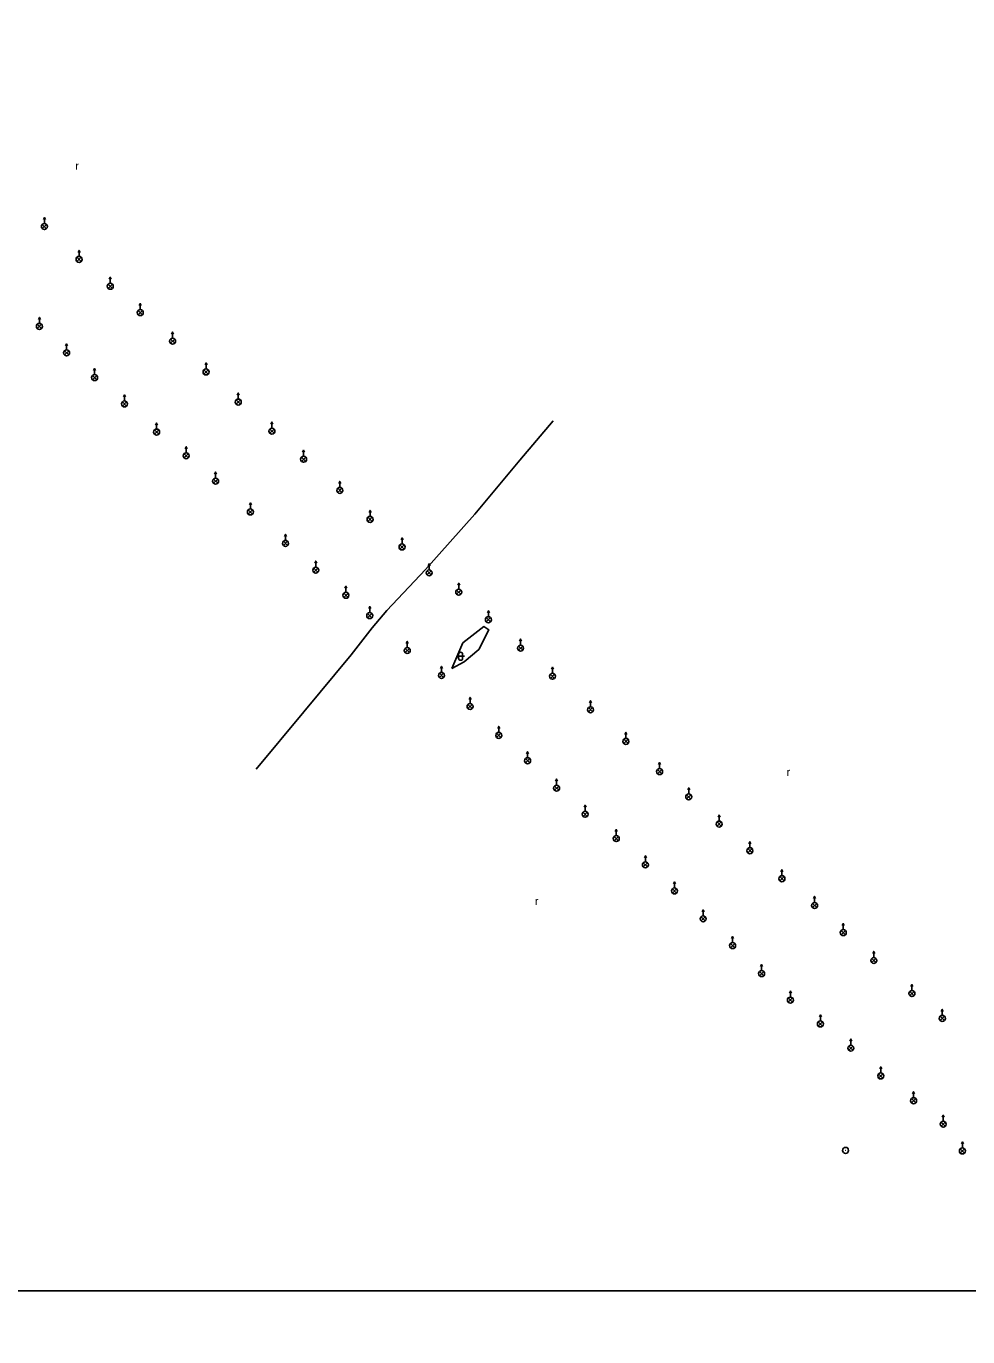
# Model space of a CAD drawing. Extents: x -582188 to -561562, y -1187250 to -1183500.
# Drawn here: x -578402.2 to -578284.6, y -1186755.7 to -1186592 of the extents above; entities that cross this region are included whole.
import ezdxf

# ---------------------------------------------------------------- set-up
doc = ezdxf.new("R2010")
doc.units = 0
for name, color, linetype in [('MAP_ZN_BP', 7, 'Continuous'), ('RÁMY_ML', 7, 'Continuous'), ('ZELEŇ', 7, 'Continuous'), ('ZN_BP', 7, 'Continuous'), ('ZN_KULTUR', 7, 'Continuous')]:
    doc.layers.add(name, color=color, linetype=linetype)

msp = doc.modelspace()

# ---------------------------------------------------------------- linework, layer by layer
at = {"layer": 'MAP_ZN_BP'}
for radius in [0.375, 0.0005]:
    msp.add_circle((-578299.84, -1186732.431), radius, dxfattribs=at)
at = {"layer": 'RÁMY_ML'}
msp.add_lwpolyline([(-578750, -1186250), (-578437.5, -1186250), (-578437.5, -1186500), (-578437.5, -1186750), (-578125, -1186750), (-578125, -1187000), (-578437.5, -1187000), (-578437.5, -1186750)], dxfattribs=at)
at = {"layer": 'ZELEŇ'}
for points in [[(-578352.3, -1186659.86), (-578346.17, -1186652.95), (-578340.51, -1186646.22), (-578336.37, -1186641.31)], [(-578352.3, -1186659.86), (-578357.15, -1186664.98), (-578358.96, -1186667.15), (-578361.58, -1186670.51), (-578367.5, -1186677.64), (-578373.45, -1186684.83)], [(-578349.02, -1186672.24), (-578347.64, -1186669.04), (-578345.04, -1186666.99), (-578344.39, -1186667.42), (-578345.67, -1186669.84), (-578347.49, -1186671.4), (-578349.02, -1186672.24)]]:
    msp.add_lwpolyline(points, dxfattribs=at)
at = {"layer": 'ZN_BP'}
for p, q in [((-578399.92, -1186616.645), (-578399.92, -1186615.895)), ((-578400.185, -1186617.284), (-578399.656, -1186616.756)), ((-578399.656, -1186617.288), (-578400.185, -1186616.756)), ((-578395.855, -1186621.394), (-578395.326, -1186620.866)), ((-578395.326, -1186621.398), (-578395.855, -1186620.866)), ((-578395.59, -1186620.755), (-578395.59, -1186620.005)), ((-578391.955, -1186624.754), (-578391.426, -1186624.226)), ((-578391.426, -1186624.758), (-578391.955, -1186624.226)), ((-578391.69, -1186624.115), (-578391.69, -1186623.365)), ((-578388.215, -1186628.044), (-578387.686, -1186627.516)), ((-578387.686, -1186628.048), (-578388.215, -1186627.516)), ((-578387.95, -1186627.405), (-578387.95, -1186626.655)), ((-578400.815, -1186629.764), (-578400.286, -1186629.236)), ((-578400.286, -1186629.768), (-578400.815, -1186629.236)), ((-578400.55, -1186629.125), (-578400.55, -1186628.375)), ((-578384.175, -1186631.604), (-578383.646, -1186631.076)), ((-578383.646, -1186631.608), (-578384.175, -1186631.076)), ((-578383.91, -1186630.965), (-578383.91, -1186630.215)), ((-578397.415, -1186633.064), (-578396.886, -1186632.536)), ((-578396.886, -1186633.068), (-578397.415, -1186632.536)), ((-578397.15, -1186632.425), (-578397.15, -1186631.675)), ((-578379.73, -1186634.815), (-578379.73, -1186634.065)), ((-578393.915, -1186636.164), (-578393.386, -1186635.636)), ((-578393.386, -1186636.168), (-578393.915, -1186635.636)), ((-578393.65, -1186635.525), (-578393.65, -1186634.775)), ((-578379.995, -1186635.454), (-578379.466, -1186634.926)), ((-578379.466, -1186635.458), (-578379.995, -1186634.926)), ((-578375.7, -1186638.575), (-578375.7, -1186637.825)), ((-578390.185, -1186639.444), (-578389.656, -1186638.916)), ((-578389.656, -1186639.448), (-578390.185, -1186638.916)), ((-578389.92, -1186638.805), (-578389.92, -1186638.055)), ((-578375.965, -1186639.214), (-578375.436, -1186638.686)), ((-578375.436, -1186639.218), (-578375.965, -1186638.686)), ((-578386.165, -1186642.954), (-578385.636, -1186642.426)), ((-578385.636, -1186642.958), (-578386.165, -1186642.426)), ((-578385.9, -1186642.315), (-578385.9, -1186641.565)), ((-578371.765, -1186642.844), (-578371.236, -1186642.316)), ((-578371.236, -1186642.848), (-578371.765, -1186642.316)), ((-578371.5, -1186642.205), (-578371.5, -1186641.455)), ((-578382.475, -1186645.924), (-578381.946, -1186645.396)), ((-578381.946, -1186645.928), (-578382.475, -1186645.396)), ((-578382.21, -1186645.285), (-578382.21, -1186644.535)), ((-578367.805, -1186646.354), (-578367.276, -1186645.826)), ((-578367.276, -1186646.358), (-578367.805, -1186645.826)), ((-578367.54, -1186645.715), (-578367.54, -1186644.965)), ((-578378.805, -1186649.094), (-578378.276, -1186648.566)), ((-578378.276, -1186649.098), (-578378.805, -1186648.566)), ((-578378.54, -1186648.455), (-578378.54, -1186647.705)), ((-578363.02, -1186649.605), (-578363.02, -1186648.855)), ((-578363.285, -1186650.244), (-578362.756, -1186649.716)), ((-578362.756, -1186650.248), (-578363.285, -1186649.716)), ((-578374.455, -1186652.944), (-578373.926, -1186652.416)), ((-578373.926, -1186652.948), (-578374.455, -1186652.416)), ((-578374.19, -1186652.305), (-578374.19, -1186651.555)), ((-578359.24, -1186653.235), (-578359.24, -1186652.485)), ((-578359.505, -1186653.874), (-578358.976, -1186653.346)), ((-578358.976, -1186653.878), (-578359.505, -1186653.346)), ((-578369.8, -1186656.225), (-578369.8, -1186655.475)), ((-578370.065, -1186656.864), (-578369.536, -1186656.336)), ((-578369.536, -1186656.868), (-578370.065, -1186656.336)), ((-578355.515, -1186657.314), (-578354.986, -1186656.786)), ((-578354.986, -1186657.318), (-578355.515, -1186656.786)), ((-578355.25, -1186656.675), (-578355.25, -1186655.925)), ((-578366.02, -1186659.575), (-578366.02, -1186658.825)), ((-578366.285, -1186660.214), (-578365.756, -1186659.686)), ((-578365.756, -1186660.218), (-578366.285, -1186659.686)), ((-578352.125, -1186660.544), (-578351.596, -1186660.016)), ((-578351.596, -1186660.548), (-578352.125, -1186660.016)), ((-578351.86, -1186659.905), (-578351.86, -1186659.155)), ((-578362.26, -1186662.715), (-578362.26, -1186661.965)), ((-578348.17, -1186662.325), (-578348.17, -1186661.575)), ((-578362.525, -1186663.354), (-578361.996, -1186662.826)), ((-578361.996, -1186663.358), (-578362.525, -1186662.826)), ((-578348.435, -1186662.964), (-578347.906, -1186662.436)), ((-578347.906, -1186662.968), (-578348.435, -1186662.436)), ((-578359.545, -1186665.894), (-578359.016, -1186665.366)), ((-578359.016, -1186665.898), (-578359.545, -1186665.366)), ((-578359.28, -1186665.255), (-578359.28, -1186664.505)), ((-578344.46, -1186665.765), (-578344.46, -1186665.015)), ((-578344.725, -1186666.404), (-578344.196, -1186665.876)), ((-578344.196, -1186666.408), (-578344.725, -1186665.876)), ((-578354.59, -1186669.605), (-578354.59, -1186668.855)), ((-578340.44, -1186669.315), (-578340.44, -1186668.565)), ((-578354.855, -1186670.244), (-578354.326, -1186669.716)), ((-578354.326, -1186670.248), (-578354.855, -1186669.716)), ((-578340.705, -1186669.954), (-578340.176, -1186669.426)), ((-578340.176, -1186669.958), (-578340.705, -1186669.426)), ((-578350.32, -1186672.725), (-578350.32, -1186671.975)), ((-578336.45, -1186672.825), (-578336.45, -1186672.075)), ((-578350.585, -1186673.364), (-578350.056, -1186672.836)), ((-578350.056, -1186673.368), (-578350.585, -1186672.836)), ((-578336.715, -1186673.464), (-578336.186, -1186672.936)), ((-578336.186, -1186673.468), (-578336.715, -1186672.936)), ((-578347.015, -1186677.244), (-578346.486, -1186676.716)), ((-578346.486, -1186677.248), (-578347.015, -1186676.716)), ((-578346.75, -1186676.605), (-578346.75, -1186675.855)), ((-578331.7, -1186677.015), (-578331.7, -1186676.265)), ((-578331.965, -1186677.654), (-578331.436, -1186677.126)), ((-578331.436, -1186677.658), (-578331.965, -1186677.126)), ((-578343.425, -1186680.854), (-578342.896, -1186680.326)), ((-578342.896, -1186680.858), (-578343.425, -1186680.326)), ((-578343.16, -1186680.215), (-578343.16, -1186679.465)), ((-578327.28, -1186680.965), (-578327.28, -1186680.215)), ((-578327.545, -1186681.604), (-578327.016, -1186681.076)), ((-578327.016, -1186681.608), (-578327.545, -1186681.076)), ((-578339.825, -1186684.024), (-578339.296, -1186683.496)), ((-578339.296, -1186684.028), (-578339.825, -1186683.496)), ((-578339.56, -1186683.385), (-578339.56, -1186682.635)), ((-578323.335, -1186685.384), (-578322.806, -1186684.856)), ((-578322.806, -1186685.388), (-578323.335, -1186684.856)), ((-578323.07, -1186684.745), (-578323.07, -1186683.995)), ((-578336.205, -1186687.444), (-578335.676, -1186686.916)), ((-578335.676, -1186687.448), (-578336.205, -1186686.916)), ((-578335.94, -1186686.805), (-578335.94, -1186686.055)), ((-578319.695, -1186688.534), (-578319.166, -1186688.006)), ((-578319.166, -1186688.538), (-578319.695, -1186688.006)), ((-578319.43, -1186687.895), (-578319.43, -1186687.145)), ((-578332.635, -1186690.704), (-578332.106, -1186690.176)), ((-578332.106, -1186690.708), (-578332.635, -1186690.176)), ((-578332.37, -1186690.065), (-578332.37, -1186689.315)), ((-578315.895, -1186691.934), (-578315.366, -1186691.406)), ((-578315.366, -1186691.938), (-578315.895, -1186691.406)), ((-578315.63, -1186691.295), (-578315.63, -1186690.545)), ((-578328.745, -1186693.744), (-578328.216, -1186693.216)), ((-578328.216, -1186693.748), (-578328.745, -1186693.216)), ((-578328.48, -1186693.105), (-578328.48, -1186692.355)), ((-578312.055, -1186695.264), (-578311.526, -1186694.736)), ((-578311.526, -1186695.268), (-578312.055, -1186694.736)), ((-578311.79, -1186694.625), (-578311.79, -1186693.875)), ((-578325.115, -1186697.024), (-578324.586, -1186696.496)), ((-578324.586, -1186697.028), (-578325.115, -1186696.496)), ((-578324.85, -1186696.385), (-578324.85, -1186695.635)), ((-578308.045, -1186698.764), (-578307.516, -1186698.236)), ((-578307.516, -1186698.768), (-578308.045, -1186698.236)), ((-578307.78, -1186698.125), (-578307.78, -1186697.375)), ((-578321.475, -1186700.294), (-578320.946, -1186699.766)), ((-578320.946, -1186700.298), (-578321.475, -1186699.766)), ((-578321.21, -1186699.655), (-578321.21, -1186698.905)), ((-578303.975, -1186702.104), (-578303.446, -1186701.576)), ((-578303.446, -1186702.108), (-578303.975, -1186701.576)), ((-578303.71, -1186701.465), (-578303.71, -1186700.715)), ((-578317.895, -1186703.774), (-578317.366, -1186703.246)), ((-578317.366, -1186703.778), (-578317.895, -1186703.246)), ((-578317.63, -1186703.135), (-578317.63, -1186702.385)), ((-578300.12, -1186704.855), (-578300.12, -1186704.105)), ((-578314.215, -1186707.114), (-578313.686, -1186706.586)), ((-578313.686, -1186707.118), (-578314.215, -1186706.586)), ((-578313.95, -1186706.475), (-578313.95, -1186705.725)), ((-578300.385, -1186705.494), (-578299.856, -1186704.966)), ((-578299.856, -1186705.498), (-578300.385, -1186704.966)), ((-578296.31, -1186708.335), (-578296.31, -1186707.585)), ((-578310.32, -1186709.975), (-578310.32, -1186709.225)), ((-578296.575, -1186708.974), (-578296.046, -1186708.446)), ((-578296.046, -1186708.978), (-578296.575, -1186708.446)), ((-578310.585, -1186710.614), (-578310.056, -1186710.086)), ((-578310.056, -1186710.618), (-578310.585, -1186710.086)), ((-578306.73, -1186713.285), (-578306.73, -1186712.535)), ((-578291.805, -1186713.104), (-578291.276, -1186712.576)), ((-578291.276, -1186713.108), (-578291.805, -1186712.576)), ((-578291.54, -1186712.465), (-578291.54, -1186711.715)), ((-578306.995, -1186713.924), (-578306.466, -1186713.396)), ((-578306.466, -1186713.928), (-578306.995, -1186713.396)), ((-578303.245, -1186716.904), (-578302.716, -1186716.376)), ((-578302.716, -1186716.908), (-578303.245, -1186716.376)), ((-578302.98, -1186716.265), (-578302.98, -1186715.515)), ((-578288.015, -1186716.204), (-578287.486, -1186715.676)), ((-578287.486, -1186716.208), (-578288.015, -1186715.676)), ((-578287.75, -1186715.565), (-578287.75, -1186714.815)), ((-578299.445, -1186719.924), (-578298.916, -1186719.396)), ((-578298.916, -1186719.928), (-578299.445, -1186719.396)), ((-578299.18, -1186719.285), (-578299.18, -1186718.535)), ((-578295.705, -1186723.394), (-578295.176, -1186722.866)), ((-578295.176, -1186723.398), (-578295.705, -1186722.866)), ((-578295.44, -1186722.755), (-578295.44, -1186722.005)), ((-578291.605, -1186726.494), (-578291.076, -1186725.966)), ((-578291.076, -1186726.498), (-578291.605, -1186725.966)), ((-578291.34, -1186725.855), (-578291.34, -1186725.105)), ((-578287.905, -1186729.424), (-578287.376, -1186728.896)), ((-578287.376, -1186729.428), (-578287.905, -1186728.896)), ((-578287.64, -1186728.785), (-578287.64, -1186728.035)), ((-578285.515, -1186732.774), (-578284.986, -1186732.246)), ((-578284.986, -1186732.778), (-578285.515, -1186732.246)), ((-578285.25, -1186732.135), (-578285.25, -1186731.385))]:
    msp.add_line(p, q, dxfattribs=at)
for points in [[(-578400.045, -1186616.145), (-578399.92, -1186615.895), (-578399.795, -1186616.145)], [(-578395.715, -1186620.255), (-578395.59, -1186620.005), (-578395.465, -1186620.255)], [(-578391.815, -1186623.615), (-578391.69, -1186623.365), (-578391.565, -1186623.615)], [(-578388.075, -1186626.905), (-578387.95, -1186626.655), (-578387.825, -1186626.905)], [(-578400.675, -1186628.625), (-578400.55, -1186628.375), (-578400.425, -1186628.625)], [(-578384.035, -1186630.465), (-578383.91, -1186630.215), (-578383.785, -1186630.465)], [(-578397.275, -1186631.925), (-578397.15, -1186631.675), (-578397.025, -1186631.925)], [(-578379.855, -1186634.315), (-578379.73, -1186634.065), (-578379.605, -1186634.315)], [(-578393.775, -1186635.025), (-578393.65, -1186634.775), (-578393.525, -1186635.025)], [(-578375.825, -1186638.075), (-578375.7, -1186637.825), (-578375.575, -1186638.075)], [(-578390.045, -1186638.305), (-578389.92, -1186638.055), (-578389.795, -1186638.305)], [(-578386.025, -1186641.815), (-578385.9, -1186641.565), (-578385.775, -1186641.815)], [(-578371.625, -1186641.705), (-578371.5, -1186641.455), (-578371.375, -1186641.705)], [(-578382.335, -1186644.785), (-578382.21, -1186644.535), (-578382.085, -1186644.785)], [(-578367.665, -1186645.215), (-578367.54, -1186644.965), (-578367.415, -1186645.215)], [(-578378.665, -1186647.955), (-578378.54, -1186647.705), (-578378.415, -1186647.955)], [(-578363.145, -1186649.105), (-578363.02, -1186648.855), (-578362.895, -1186649.105)], [(-578374.315, -1186651.805), (-578374.19, -1186651.555), (-578374.065, -1186651.805)], [(-578359.365, -1186652.735), (-578359.24, -1186652.485), (-578359.115, -1186652.735)], [(-578369.925, -1186655.725), (-578369.8, -1186655.475), (-578369.675, -1186655.725)], [(-578355.375, -1186656.175), (-578355.25, -1186655.925), (-578355.125, -1186656.175)], [(-578366.145, -1186659.075), (-578366.02, -1186658.825), (-578365.895, -1186659.075)], [(-578351.985, -1186659.405), (-578351.86, -1186659.155), (-578351.735, -1186659.405)], [(-578362.385, -1186662.215), (-578362.26, -1186661.965), (-578362.135, -1186662.215)], [(-578348.295, -1186661.825), (-578348.17, -1186661.575), (-578348.045, -1186661.825)], [(-578359.405, -1186664.755), (-578359.28, -1186664.505), (-578359.155, -1186664.755)], [(-578344.585, -1186665.265), (-578344.46, -1186665.015), (-578344.335, -1186665.265)], [(-578354.715, -1186669.105), (-578354.59, -1186668.855), (-578354.465, -1186669.105)], [(-578340.565, -1186668.815), (-578340.44, -1186668.565), (-578340.315, -1186668.815)], [(-578350.445, -1186672.225), (-578350.32, -1186671.975), (-578350.195, -1186672.225)], [(-578336.575, -1186672.325), (-578336.45, -1186672.075), (-578336.325, -1186672.325)], [(-578346.875, -1186676.105), (-578346.75, -1186675.855), (-578346.625, -1186676.105)], [(-578331.825, -1186676.515), (-578331.7, -1186676.265), (-578331.575, -1186676.515)], [(-578343.285, -1186679.715), (-578343.16, -1186679.465), (-578343.035, -1186679.715)], [(-578327.405, -1186680.465), (-578327.28, -1186680.215), (-578327.155, -1186680.465)], [(-578339.685, -1186682.885), (-578339.56, -1186682.635), (-578339.435, -1186682.885)], [(-578323.195, -1186684.245), (-578323.07, -1186683.995), (-578322.945, -1186684.245)], [(-578336.065, -1186686.305), (-578335.94, -1186686.055), (-578335.815, -1186686.305)], [(-578319.555, -1186687.395), (-578319.43, -1186687.145), (-578319.305, -1186687.395)], [(-578332.495, -1186689.565), (-578332.37, -1186689.315), (-578332.245, -1186689.565)], [(-578315.755, -1186690.795), (-578315.63, -1186690.545), (-578315.505, -1186690.795)], [(-578328.605, -1186692.605), (-578328.48, -1186692.355), (-578328.355, -1186692.605)], [(-578311.915, -1186694.125), (-578311.79, -1186693.875), (-578311.665, -1186694.125)], [(-578324.975, -1186695.885), (-578324.85, -1186695.635), (-578324.725, -1186695.885)], [(-578307.905, -1186697.625), (-578307.78, -1186697.375), (-578307.655, -1186697.625)], [(-578321.335, -1186699.155), (-578321.21, -1186698.905), (-578321.085, -1186699.155)], [(-578303.835, -1186700.965), (-578303.71, -1186700.715), (-578303.585, -1186700.965)], [(-578317.755, -1186702.635), (-578317.63, -1186702.385), (-578317.505, -1186702.635)], [(-578300.245, -1186704.355), (-578300.12, -1186704.105), (-578299.995, -1186704.355)], [(-578314.075, -1186705.975), (-578313.95, -1186705.725), (-578313.825, -1186705.975)], [(-578296.435, -1186707.835), (-578296.31, -1186707.585), (-578296.185, -1186707.835)], [(-578310.445, -1186709.475), (-578310.32, -1186709.225), (-578310.195, -1186709.475)], [(-578306.855, -1186712.785), (-578306.73, -1186712.535), (-578306.605, -1186712.785)], [(-578291.665, -1186711.965), (-578291.54, -1186711.715), (-578291.415, -1186711.965)], [(-578303.105, -1186715.765), (-578302.98, -1186715.515), (-578302.855, -1186715.765)], [(-578287.875, -1186715.065), (-578287.75, -1186714.815), (-578287.625, -1186715.065)], [(-578299.305, -1186718.785), (-578299.18, -1186718.535), (-578299.055, -1186718.785)], [(-578295.565, -1186722.255), (-578295.44, -1186722.005), (-578295.315, -1186722.255)], [(-578291.465, -1186725.355), (-578291.34, -1186725.105), (-578291.215, -1186725.355)], [(-578287.765, -1186728.285), (-578287.64, -1186728.035), (-578287.515, -1186728.285)], [(-578285.375, -1186731.635), (-578285.25, -1186731.385), (-578285.125, -1186731.635)]]:
    msp.add_lwpolyline(points, dxfattribs=at)
for centre in [(-578399.92, -1186617.02), (-578395.59, -1186621.13), (-578391.69, -1186624.49), (-578387.95, -1186627.78), (-578400.55, -1186629.5), (-578383.91, -1186631.34), (-578397.15, -1186632.8), (-578393.65, -1186635.9), (-578379.73, -1186635.19), (-578389.92, -1186639.18), (-578375.7, -1186638.95), (-578385.9, -1186642.69), (-578371.5, -1186642.58), (-578382.21, -1186645.66), (-578367.54, -1186646.09), (-578378.54, -1186648.83), (-578363.02, -1186649.98), (-578374.19, -1186652.68), (-578359.24, -1186653.61), (-578369.8, -1186656.6), (-578355.25, -1186657.05), (-578366.02, -1186659.95), (-578351.86, -1186660.28), (-578348.17, -1186662.7), (-578362.26, -1186663.09), (-578359.28, -1186665.63), (-578344.46, -1186666.14), (-578354.59, -1186669.98), (-578340.44, -1186669.69), (-578350.32, -1186673.1), (-578336.45, -1186673.2), (-578346.75, -1186676.98), (-578331.7, -1186677.39), (-578343.16, -1186680.59), (-578327.28, -1186681.34), (-578339.56, -1186683.76), (-578323.07, -1186685.12), (-578335.94, -1186687.18), (-578319.43, -1186688.27), (-578332.37, -1186690.44), (-578315.63, -1186691.67), (-578328.48, -1186693.48), (-578311.79, -1186695), (-578324.85, -1186696.76), (-578307.78, -1186698.5), (-578321.21, -1186700.03), (-578303.71, -1186701.84), (-578317.63, -1186703.51), (-578300.12, -1186705.23), (-578313.95, -1186706.85), (-578296.31, -1186708.71), (-578310.32, -1186710.35), (-578291.54, -1186712.84), (-578306.73, -1186713.66), (-578302.98, -1186716.64), (-578287.75, -1186715.94), (-578299.18, -1186719.66), (-578295.44, -1186723.13), (-578291.34, -1186726.23), (-578287.64, -1186729.16), (-578285.25, -1186732.51)]:
    msp.add_circle(centre, 0.375, dxfattribs=at)
at = {"layer": 'ZN_KULTUR'}
for p, q in [((-578348.18, -1186670.96), (-578348.18, -1186670.46)), ((-578347.68, -1186670.96), (-578347.68, -1186670.46)), ((-578348.43, -1186670.71), (-578347.43, -1186670.71))]:
    msp.add_line(p, q, dxfattribs=at)
for centre, start, end in [((-578347.93, -1186670.46), 0, 179.99999), ((-578347.93, -1186670.96), 179.99999, 359.99999)]:
    msp.add_arc(centre, 0.25, start, end, dxfattribs=at)

# ---------------------------------------------------------------- texts
for p in [(-578396.048, -1186609.932), (-578307.198, -1186685.672), (-578338.638, -1186701.792)]:
    msp.add_text('r', height=1, dxfattribs=at).set_placement(p)

doc.saveas('drawing.dxf')
